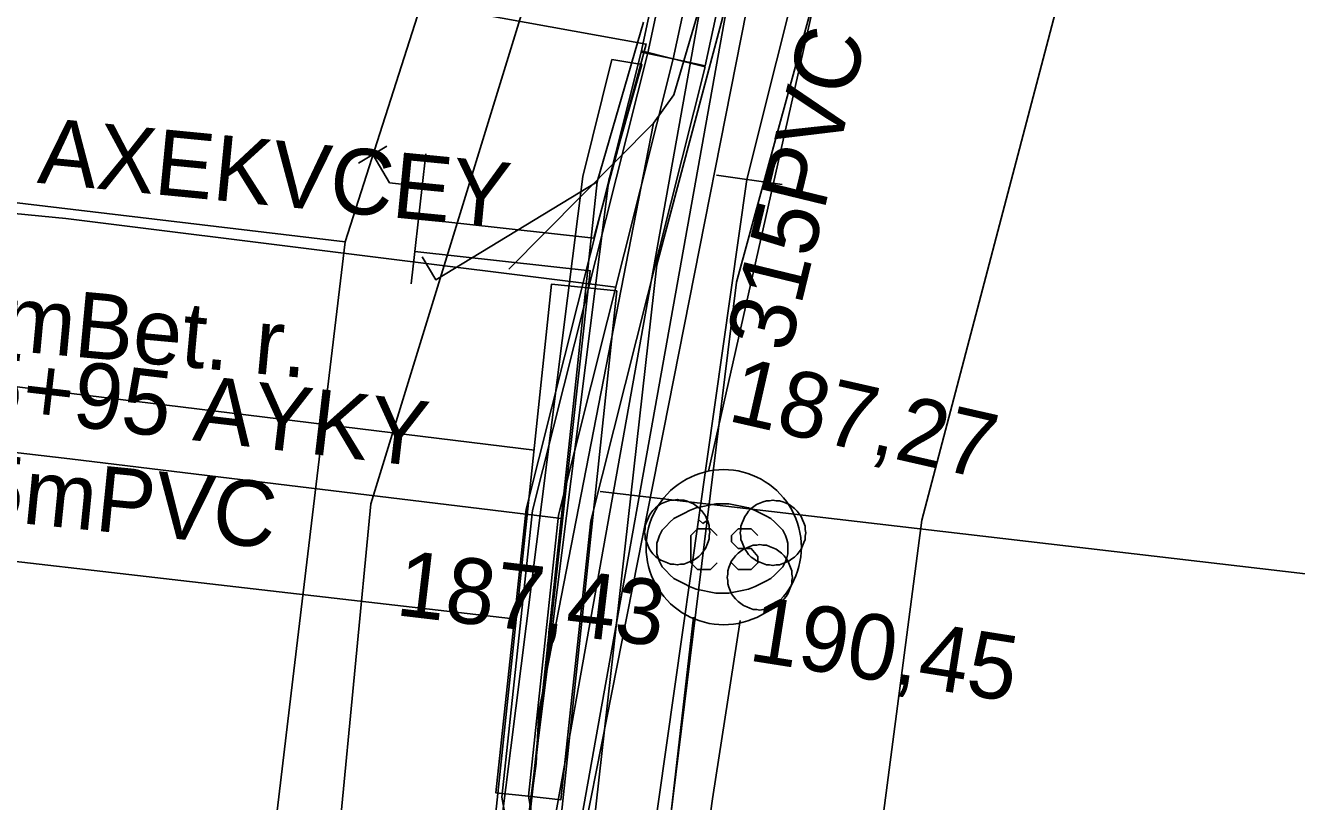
# Model space of a CAD drawing. Extents: x -746464 to -745690, y -1051581 to -1049993.
# Drawn here: x -746123.17 to -746103.78, y -1050733.16 to -1050721.32 of the extents above; entities that cross this region are included whole.
import ezdxf

# ---------------------------------------------------------------- set-up
doc = ezdxf.new("R2010")
doc.units = 0
for name, color, linetype in [('04_CETIN_neprovozovane', 7, 'Continuous'), ('04_CETIN_sdelovaci_podzem', 7, 'Continuous'), ('37_TVNET_sdelovaci_televizni kabely', 7, 'Continuous'), ('45_Eltodo_napajeci_kabel_NN', 7, 'Continuous'), ('45_Eltodo_vedeni_NN_zemni', 7, 'Continuous'), ('48_Prazs_plynarenska_STL', 7, 'Continuous'), ('51_PVaK_kanal_jednotna_overena poloha_rad', 7, 'Continuous'), ('51_PVaK_kanal_negravitacni_overena poloha', 7, 'Continuous'), ('51_PVaK_kanal_objekty', 7, 'Continuous'), ('51_PVaK_kanal_popisy', 7, 'Continuous'), ('51_PVaK_vodovod_chranicky_objekty', 7, 'Continuous'), ('51_PVaK_vodovod_NEPROVOZUJE PVK_neoverene poloha', 7, 'Continuous'), ('55_PREdi_chranicky', 7, 'Continuous'), ('55_PREdi_NN', 7, 'Continuous'), ('55_PREdi_NN_popisy', 7, 'Continuous'), ('55_PREdi_NN_pripojovaci_misto', 7, 'Continuous'), ('55_PREdi_stavby_popisy', 7, 'Continuous'), ('55_PREdi_VN', 7, 'Continuous'), ('55_PREdi_VN_popisy', 7, 'Continuous'), ('55_PREdi_ZRUSENE_elektro', 7, 'Continuous')]:
    doc.layers.add(name, color=color, linetype=linetype)

msp = doc.modelspace()

# ---------------------------------------------------------------- linework, layer by layer
at = {"layer": '04_CETIN_neprovozovane'}
msp.add_lwpolyline([(-746122.86, -1050802.08), (-746120.21, -1050779.57), (-746117.76, -1050758.96), (-746115.41, -1050737.5), (-746111.78, -1050719.1), (-746081.26, -1050611.75), (-746077.75, -1050600.04)], dxfattribs=at)
at = {"layer": '04_CETIN_sdelovaci_podzem'}
for points in [[(-746113.59, -1050722.81), (-746113.28, -1050722.38), (-746111.9, -1050717.67)], [(-746113.59, -1050722.81), (-746115.8, -1050725.04)], [(-746115.67, -1050734.71), (-746115.38, -1050732.58), (-746115.34, -1050731.79), (-746113.59, -1050722.81)]]:
    msp.add_lwpolyline(points, dxfattribs=at)
at = {"layer": '37_TVNET_sdelovaci_televizni kabely'}
for points in [[(-745984.595, -1050626.363), (-746079.15, -1050602.616), (-746117.902, -1050728.62), (-746140.499, -1050964.785), (-746150.343, -1051014.385), (-746134.374, -1051025.766), (-746053.56, -1051028.358)], [(-746118.296, -1050724.621), (-746094.89, -1050651.467), (-746102.801, -1050648.936)], [(-746121.771, -1050753.802), (-746119.076, -1050731.167), (-746118.296, -1050724.621), (-746124.842, -1050723.842)]]:
    msp.add_lwpolyline(points, dxfattribs=at)
at = {"layer": '45_Eltodo_napajeci_kabel_NN'}
msp.add_lwpolyline([(-746120.222, -1050780.456), (-746117.893, -1050761.331), (-746115.771, -1050739.469), (-746111.954, -1050718.14), (-746112.159, -1050718.76), (-746102.169, -1050679.37), (-746100.421, -1050672.083), (-746096.865, -1050659.485), (-746093.587, -1050648.313), (-746077.373, -1050597.206), (-746063.594, -1050600.606), (-746044.898, -1050606.017), (-746045.886, -1050609.461)], dxfattribs=at)
at = {"layer": '45_Eltodo_vedeni_NN_zemni'}
msp.add_lwpolyline([(-746116.168, -1050739.414), (-746112.348, -1050718.07)], dxfattribs=at)
at = {"layer": '48_Prazs_plynarenska_STL'}
msp.add_lwpolyline([(-746115.164, -1050775.276), (-746114.581, -1050769.606), (-746114.401, -1050767.848), (-746113.67, -1050760.737), (-746113.57, -1050759.76), (-746112.697, -1050753.167), (-746110.88, -1050739.44), (-746109.5, -1050728.87), (-746105.616, -1050714.089), (-746102.18, -1050701.01), (-746092.81, -1050669.78), (-746086.791, -1050645.246), (-746082.87, -1050630.67), (-746075.19, -1050609.92), (-746073.343, -1050606.911), (-746072.119, -1050604.92)], dxfattribs=at)
at = {"layer": '51_PVaK_kanal_jednotna_overena poloha_rad'}
msp.add_line((-746110.62, -1050718.65), (-746112.75, -1050728.12), dxfattribs=at)
msp.add_lwpolyline([(-746116.83, -1050763.77), (-746116.059, -1050757.073), (-746113.735, -1050736.907), (-746112.98, -1050730.35)], dxfattribs=at)
at = {"layer": '51_PVaK_kanal_negravitacni_overena poloha'}
msp.add_lwpolyline([(-746112.27, -1050730.4), (-746112.69, -1050733.12), (-746114.09, -1050743.18), (-746115.12, -1050753.61)], dxfattribs=at)
at = {"layer": '51_PVaK_kanal_objekty'}
for q in [(-746112.9, -1050728.86), (-746112.76, -1050728.86)]:
    msp.add_line((-746112.84, -1050728.92), q, dxfattribs=at)
msp.add_lwpolyline([(-746111.336, -1050729.28), (-746111.339, -1050729.354), (-746111.346, -1050729.428), (-746111.357, -1050729.502), (-746111.374, -1050729.574), (-746111.394, -1050729.646), (-746111.42, -1050729.716), (-746111.449, -1050729.784), (-746111.483, -1050729.85), (-746111.521, -1050729.914), (-746111.563, -1050729.976), (-746111.608, -1050730.034), (-746111.657, -1050730.09), (-746111.71, -1050730.143), (-746111.766, -1050730.192), (-746111.824, -1050730.238), (-746111.886, -1050730.279), (-746111.95, -1050730.317), (-746112.016, -1050730.351), (-746112.084, -1050730.38), (-746112.154, -1050730.406), (-746112.226, -1050730.426), (-746112.298, -1050730.443), (-746112.372, -1050730.454), (-746112.446, -1050730.461), (-746112.52, -1050730.464), (-746112.594, -1050730.461), (-746112.668, -1050730.454), (-746112.742, -1050730.443), (-746112.814, -1050730.426), (-746112.886, -1050730.406), (-746112.956, -1050730.38), (-746113.024, -1050730.351), (-746113.09, -1050730.317), (-746113.154, -1050730.279), (-746113.216, -1050730.238), (-746113.274, -1050730.192), (-746113.33, -1050730.143), (-746113.383, -1050730.09), (-746113.432, -1050730.034), (-746113.477, -1050729.976), (-746113.519, -1050729.914), (-746113.557, -1050729.85), (-746113.591, -1050729.784), (-746113.62, -1050729.716), (-746113.646, -1050729.646), (-746113.666, -1050729.574), (-746113.683, -1050729.502), (-746113.694, -1050729.428), (-746113.701, -1050729.354), (-746113.704, -1050729.28), (-746113.701, -1050729.206), (-746113.694, -1050729.132), (-746113.683, -1050729.058), (-746113.666, -1050728.986), (-746113.646, -1050728.914), (-746113.62, -1050728.844), (-746113.591, -1050728.776), (-746113.557, -1050728.71), (-746113.519, -1050728.646), (-746113.477, -1050728.584), (-746113.432, -1050728.526), (-746113.383, -1050728.47), (-746113.33, -1050728.417), (-746113.274, -1050728.368), (-746113.216, -1050728.323), (-746113.154, -1050728.281), (-746113.09, -1050728.243), (-746113.024, -1050728.209), (-746112.956, -1050728.18), (-746112.886, -1050728.154), (-746112.814, -1050728.134), (-746112.742, -1050728.117), (-746112.668, -1050728.106), (-746112.594, -1050728.099), (-746112.52, -1050728.096), (-746112.446, -1050728.099), (-746112.372, -1050728.106), (-746112.298, -1050728.117), (-746112.226, -1050728.134), (-746112.154, -1050728.154), (-746112.084, -1050728.18), (-746112.016, -1050728.209), (-746111.95, -1050728.243), (-746111.886, -1050728.281), (-746111.824, -1050728.323), (-746111.766, -1050728.368), (-746111.71, -1050728.417), (-746111.657, -1050728.47), (-746111.608, -1050728.526), (-746111.563, -1050728.584), (-746111.521, -1050728.646), (-746111.483, -1050728.71), (-746111.449, -1050728.776), (-746111.42, -1050728.844), (-746111.394, -1050728.914), (-746111.374, -1050728.986), (-746111.357, -1050729.058), (-746111.346, -1050729.132), (-746111.339, -1050729.206)], close=True, dxfattribs=at)
for points in [[(-746112.73, -1050729.05), (-746112.74, -1050729), (-746112.74, -1050728.95), (-746112.76, -1050728.9), (-746112.78, -1050728.85), (-746112.8, -1050728.8), (-746112.83, -1050728.76), (-746112.86, -1050728.72), (-746112.9, -1050728.68), (-746112.94, -1050728.65), (-746112.98, -1050728.62), (-746113.03, -1050728.6), (-746113.08, -1050728.58), (-746113.13, -1050728.56), (-746113.18, -1050728.56), (-746113.23, -1050728.55), (-746113.28, -1050728.56), (-746113.33, -1050728.56), (-746113.38, -1050728.58), (-746113.43, -1050728.6), (-746113.48, -1050728.62), (-746113.52, -1050728.65), (-746113.56, -1050728.68), (-746113.6, -1050728.72), (-746113.63, -1050728.76), (-746113.66, -1050728.8), (-746113.68, -1050728.85), (-746113.7, -1050728.9), (-746113.72, -1050728.95), (-746113.72, -1050729), (-746113.73, -1050729.05), (-746113.72, -1050729.1), (-746113.72, -1050729.15), (-746113.7, -1050729.2), (-746113.68, -1050729.25), (-746113.66, -1050729.3), (-746113.63, -1050729.34), (-746113.6, -1050729.38), (-746113.56, -1050729.42), (-746113.52, -1050729.45), (-746113.48, -1050729.48), (-746113.43, -1050729.5), (-746113.38, -1050729.52), (-746113.33, -1050729.54), (-746113.28, -1050729.54), (-746113.23, -1050729.55), (-746113.18, -1050729.54), (-746113.13, -1050729.54), (-746113.08, -1050729.52), (-746113.03, -1050729.5), (-746112.98, -1050729.48), (-746112.94, -1050729.45), (-746112.9, -1050729.42), (-746112.86, -1050729.38), (-746112.83, -1050729.34), (-746112.8, -1050729.3), (-746112.78, -1050729.25), (-746112.76, -1050729.2), (-746112.74, -1050729.15), (-746112.74, -1050729.1), (-746112.73, -1050729.05)], [(-746111.27, -1050729.06), (-746111.28, -1050729.01), (-746111.28, -1050728.96), (-746111.3, -1050728.91), (-746111.32, -1050728.86), (-746111.34, -1050728.81), (-746111.37, -1050728.77), (-746111.4, -1050728.73), (-746111.44, -1050728.69), (-746111.48, -1050728.66), (-746111.52, -1050728.63), (-746111.57, -1050728.61), (-746111.62, -1050728.59), (-746111.67, -1050728.57), (-746111.72, -1050728.57), (-746111.77, -1050728.56), (-746111.82, -1050728.57), (-746111.87, -1050728.57), (-746111.92, -1050728.59), (-746111.97, -1050728.61), (-746112.02, -1050728.63), (-746112.06, -1050728.66), (-746112.1, -1050728.69), (-746112.14, -1050728.73), (-746112.17, -1050728.77), (-746112.2, -1050728.81), (-746112.22, -1050728.86), (-746112.24, -1050728.91), (-746112.26, -1050728.96), (-746112.26, -1050729.01), (-746112.27, -1050729.06), (-746112.26, -1050729.11), (-746112.26, -1050729.16), (-746112.24, -1050729.21), (-746112.22, -1050729.26), (-746112.2, -1050729.31), (-746112.17, -1050729.35), (-746112.14, -1050729.39), (-746112.1, -1050729.43), (-746112.06, -1050729.46), (-746112.02, -1050729.49), (-746111.97, -1050729.51), (-746111.92, -1050729.53), (-746111.87, -1050729.55), (-746111.82, -1050729.55), (-746111.77, -1050729.56), (-746111.72, -1050729.55), (-746111.67, -1050729.55), (-746111.62, -1050729.53), (-746111.57, -1050729.51), (-746111.52, -1050729.49), (-746111.48, -1050729.46), (-746111.44, -1050729.43), (-746111.4, -1050729.39), (-746111.37, -1050729.35), (-746111.34, -1050729.31), (-746111.32, -1050729.26), (-746111.3, -1050729.21), (-746111.28, -1050729.16), (-746111.28, -1050729.11), (-746111.27, -1050729.06)], [(-746113.54, -1050729.3), (-746113.54, -1050729.38), (-746113.52, -1050729.44), (-746113.5, -1050729.5), (-746113.46, -1050729.58), (-746113.4, -1050729.64), (-746113.34, -1050729.7), (-746113.28, -1050729.76), (-746113.2, -1050729.8), (-746113.12, -1050729.84), (-746113.04, -1050729.88), (-746112.94, -1050729.92), (-746112.84, -1050729.94), (-746112.74, -1050729.96), (-746112.64, -1050729.98), (-746112.54, -1050729.98), (-746112.44, -1050729.98), (-746112.34, -1050729.96), (-746112.24, -1050729.94), (-746112.14, -1050729.92), (-746112.04, -1050729.88), (-746111.96, -1050729.84), (-746111.88, -1050729.8), (-746111.8, -1050729.76), (-746111.74, -1050729.7), (-746111.68, -1050729.64), (-746111.62, -1050729.58), (-746111.58, -1050729.5), (-746111.56, -1050729.44), (-746111.54, -1050729.38), (-746111.54, -1050729.3), (-746111.54, -1050729.22), (-746111.56, -1050729.16), (-746111.58, -1050729.1), (-746111.62, -1050729.02), (-746111.68, -1050728.96), (-746111.74, -1050728.9), (-746111.8, -1050728.84), (-746111.88, -1050728.8), (-746111.96, -1050728.76), (-746112.04, -1050728.72), (-746112.14, -1050728.68), (-746112.24, -1050728.66), (-746112.34, -1050728.64), (-746112.44, -1050728.62), (-746112.54, -1050728.62), (-746112.64, -1050728.62), (-746112.74, -1050728.64), (-746112.84, -1050728.66), (-746112.94, -1050728.68), (-746113.04, -1050728.72), (-746113.12, -1050728.76), (-746113.2, -1050728.8), (-746113.28, -1050728.84), (-746113.34, -1050728.9), (-746113.4, -1050728.96), (-746113.46, -1050729.02), (-746113.5, -1050729.1), (-746113.52, -1050729.16), (-746113.54, -1050729.22), (-746113.54, -1050729.3)], [(-746112.62, -1050729.52), (-746112.72, -1050729.62), (-746112.92, -1050729.62), (-746113.02, -1050729.52), (-746113.02, -1050729.1), (-746112.92, -1050729), (-746112.72, -1050729), (-746112.62, -1050729.1)], [(-746112.4, -1050729.52), (-746112.3, -1050729.62), (-746112.1, -1050729.62), (-746112, -1050729.52), (-746112, -1050729.42), (-746112.1, -1050729.3), (-746112.3, -1050729.3), (-746112.4, -1050729.2), (-746112.4, -1050729.1), (-746112.3, -1050729), (-746112.1, -1050729), (-746112, -1050729.1)], [(-746111.47, -1050729.74), (-746111.48, -1050729.69), (-746111.48, -1050729.64), (-746111.5, -1050729.59), (-746111.52, -1050729.54), (-746111.54, -1050729.49), (-746111.57, -1050729.45), (-746111.6, -1050729.41), (-746111.64, -1050729.37), (-746111.68, -1050729.34), (-746111.72, -1050729.31), (-746111.77, -1050729.29), (-746111.82, -1050729.27), (-746111.87, -1050729.25), (-746111.92, -1050729.25), (-746111.97, -1050729.24), (-746112.02, -1050729.25), (-746112.07, -1050729.25), (-746112.12, -1050729.27), (-746112.17, -1050729.29), (-746112.22, -1050729.31), (-746112.26, -1050729.34), (-746112.3, -1050729.37), (-746112.34, -1050729.41), (-746112.37, -1050729.45), (-746112.4, -1050729.49), (-746112.42, -1050729.54), (-746112.44, -1050729.59), (-746112.46, -1050729.64), (-746112.46, -1050729.69), (-746112.47, -1050729.74), (-746112.46, -1050729.79), (-746112.46, -1050729.84), (-746112.44, -1050729.89), (-746112.42, -1050729.94), (-746112.4, -1050729.99), (-746112.37, -1050730.03), (-746112.34, -1050730.07), (-746112.3, -1050730.11), (-746112.26, -1050730.14), (-746112.22, -1050730.17), (-746112.17, -1050730.19), (-746112.12, -1050730.21), (-746112.07, -1050730.23), (-746112.02, -1050730.23), (-746111.97, -1050730.24), (-746111.92, -1050730.23), (-746111.87, -1050730.23), (-746111.82, -1050730.21), (-746111.77, -1050730.19), (-746111.72, -1050730.17), (-746111.68, -1050730.14), (-746111.64, -1050730.11), (-746111.6, -1050730.07), (-746111.57, -1050730.03), (-746111.54, -1050729.99), (-746111.52, -1050729.94), (-746111.5, -1050729.89), (-746111.48, -1050729.84), (-746111.48, -1050729.79), (-746111.47, -1050729.74)]]:
    msp.add_lwpolyline(points, dxfattribs=at)
at = {"layer": '51_PVaK_vodovod_chranicky_objekty'}
msp.add_line((-746111.63, -1050723.747), (-746112.63, -1050723.605), dxfattribs=at)
at = {"layer": '51_PVaK_vodovod_NEPROVOZUJE PVK_neoverene poloha'}
for points in [[(-746081.419, -1050615.368), (-746089.682, -1050643.328), (-746097.066, -1050667.122), (-746097.128, -1050667.322), (-746108.564, -1050709.28), (-746112.17, -1050723.67)], [(-746112.17, -1050723.67), (-746115.962, -1050750.386), (-746116.764, -1050758.266), (-746119.36, -1050777.72)]]:
    msp.add_lwpolyline(points, dxfattribs=at)
at = {"layer": '55_PREdi_chranicky'}
for points in [[(-746099.15, -1050668.69), (-746098.675, -1050668.846), (-746100.87, -1050675.512), (-746102.387, -1050681.318), (-746103.889, -1050686.926), (-746105.384, -1050691.978), (-746106.221, -1050696.346), (-746107.647, -1050702.28), (-746109.299, -1050707.795), (-746111.804, -1050717.296), (-746112.801, -1050721.935), (-746113.29, -1050721.83), (-746113.779, -1050721.725), (-746112.776, -1050717.064), (-746110.261, -1050707.525), (-746108.613, -1050702.02), (-746107.199, -1050696.134), (-746106.356, -1050691.742), (-746104.851, -1050686.654), (-746103.353, -1050681.062), (-746101.83, -1050675.228), (-746099.625, -1050668.534), (-746099.15, -1050668.69)], [(-746113.29, -1050721.83), (-746112.805, -1050721.952), (-746114.547, -1050728.878), (-746115.003, -1050733.133), (-746115.5, -1050733.08), (-746115.997, -1050733.027), (-746115.533, -1050728.702), (-746113.775, -1050721.708), (-746113.29, -1050721.83)], [(-746114.225, -1050721.84), (-746113.769, -1050721.915), (-746114.275, -1050723.682), (-746115.92, -1050736.748), (-746116.316, -1050736.698), (-746114.668, -1050723.626), (-746114.225, -1050721.84)], [(-746115.201, -1050735.314), (-746116.195, -1050735.209), (-746115.145, -1050725.265), (-746114.151, -1050725.37), (-746115.201, -1050735.314)]]:
    msp.add_lwpolyline(points, close=True, dxfattribs=at)
at = {"layer": '55_PREdi_NN'}
for points in [[(-746079.707, -1050608.094), (-746081.337, -1050613.521), (-746088.598, -1050639.168), (-746100.883, -1050680.307), (-746109.804, -1050710.935), (-746113.542, -1050724.97), (-746114.797, -1050736.143), (-746116.957, -1050755.942), (-746121.273, -1050791.507), (-746121.329, -1050792.488), (-746122.44, -1050801.822), (-746124.772, -1050826.479), (-746132.514, -1050898.319), (-746135.263, -1050933.408), (-746137.115, -1050954.341), (-746141.612, -1050953.806)], [(-746078.666, -1050608.367), (-746080.547, -1050614.642), (-746087.42, -1050639.673), (-746099.733, -1050680.532), (-746108.682, -1050711.888), (-746112.327, -1050725.235), (-746113.87, -1050737.785), (-746116.087, -1050756.251), (-746119.869, -1050789.369)], [(-746120.05, -1050717.181), (-746120.127, -1050717.683), (-746120.518, -1050717.621), (-746120.967, -1050720.285), (-746113.702, -1050721.603), (-746114.501, -1050724.567), (-746117.176, -1050724.271)], [(-746113.746, -1050721.267), (-746114.449, -1050723.706)], [(-746117.286, -1050725.264), (-746117.231, -1050724.767), (-746117.176, -1050724.271), (-746117.12, -1050723.774), (-746117.065, -1050723.277)], [(-746117.12, -1050723.774), (-746117.617, -1050723.719)], [(-746114.449, -1050723.706), (-746115.673, -1050735.132), (-746117.214, -1050749.815)], [(-746117.122, -1050724.851), (-746116.912, -1050725.198), (-746114.449, -1050723.706)], [(-746117.231, -1050724.767), (-746114.556, -1050725.063), (-746115.751, -1050735.863), (-746117.126, -1050749.478), (-746125.289, -1050748.581), (-746125.093, -1050747.151), (-746125.515, -1050747.066), (-746125.379, -1050746.39)]]:
    msp.add_lwpolyline(points, dxfattribs=at)
at = {"layer": '55_PREdi_NN_popisy'}
msp.add_lwpolyline([(-746131.372, -1050726.9), (-746122.496, -1050727.933), (-746114.994, -1050728.841)], dxfattribs=at)
at = {"layer": '55_PREdi_NN_pripojovaci_misto'}
for p, q in [((-746117.66, -1050723.162), (-746118.089, -1050723.419)), ((-746117.617, -1050723.719), (-746117.875, -1050723.29))]:
    msp.add_line(p, q, dxfattribs=at)
at = {"layer": '55_PREdi_stavby_popisy'}
for points in [[(-746134.38, -1050725.766), (-746124.676, -1050726.666), (-746115.407, -1050727.798)], [(-746114.407, -1050728.431), (-746103.339, -1050729.722), (-746093.662, -1050730.881)], [(-746130.442, -1050728.692), (-746129.447, -1050728.792), (-746115.771, -1050730.369)]]:
    msp.add_lwpolyline(points, dxfattribs=at)
at = {"layer": '55_PREdi_VN'}
for points in [[(-746119.82, -1050775.83), (-746119.1, -1050768.57), (-746117.99, -1050758.17), (-746117.59, -1050754.39), (-746116.84, -1050747.88), (-746116.1, -1050741.93), (-746115.26, -1050735.57), (-746115.23, -1050734.58), (-746115.5, -1050733.08), (-746115.04, -1050728.79), (-746113.29, -1050721.83), (-746112.29, -1050717.18), (-746109.78, -1050707.66), (-746108.13, -1050702.15), (-746106.71, -1050696.24), (-746105.87, -1050691.86), (-746104.37, -1050686.79), (-746102.87, -1050681.19), (-746101.35, -1050675.37)], [(-746101.35, -1050675.37), (-746102.87, -1050681.19), (-746104.37, -1050686.79), (-746105.87, -1050691.86), (-746106.71, -1050696.24), (-746108.13, -1050702.15), (-746109.78, -1050707.66), (-746112.29, -1050717.18), (-746113.29, -1050721.83), (-746115.04, -1050728.79), (-746115.5, -1050733.08), (-746115.23, -1050734.58), (-746115.26, -1050735.57), (-746116.1, -1050741.93), (-746116.84, -1050747.88), (-746117.59, -1050754.39), (-746117.99, -1050758.17), (-746119.1, -1050768.57), (-746119.82, -1050775.83)]]:
    msp.add_lwpolyline(points, dxfattribs=at)
at = {"layer": '55_PREdi_VN_popisy'}
msp.add_lwpolyline([(-746134.35, -1050723.117), (-746122.556, -1050724.264), (-746114.165, -1050725.31)], dxfattribs=at)
at = {"layer": '55_PREdi_ZRUSENE_elektro'}
msp.add_lwpolyline([(-746120.218, -1050775.786), (-746119.498, -1050768.529), (-746118.388, -1050758.128), (-746117.988, -1050754.346), (-746117.237, -1050747.832), (-746116.497, -1050741.879), (-746115.659, -1050735.538), (-746115.631, -1050734.61), (-746115.904, -1050733.094), (-746115.435, -1050728.72), (-746113.68, -1050721.739), (-746112.679, -1050717.087), (-746110.165, -1050707.552), (-746108.516, -1050702.046), (-746107.101, -1050696.156), (-746106.259, -1050691.765), (-746104.755, -1050686.681), (-746103.257, -1050681.088), (-746101.734, -1050675.257)], dxfattribs=at)

# ---------------------------------------------------------------- texts
at = {"layer": '51_PVaK_kanal_popisy'}
for s, rotation, p in [('315PVC', 76.3239, (-746111.519, -1050726.333)), ('187,27', 347.1482, (-746112.482, -1050727.346)), ('187,43', 353.2525, (-746117.541, -1050730.315)), ('190,45', 351.0438, (-746112.163, -1050731.005))]:
    msp.add_text(s, height=1, rotation=rotation, dxfattribs=at).set_placement(p)
at = {"layer": '55_PREdi_NN_popisy'}
msp.add_text('3x185+95 AYKY', height=1, rotation=353.3602, dxfattribs=at).set_placement((-746126.876, -1050726.919))
at = {"layer": '55_PREdi_stavby_popisy'}
for s, rotation, p in [('2x20-15.0mBet. r.', 354.7013, (-746129.482, -1050725.718)), ('1x200-11,5mPVC', 354.2534, (-746129.895, -1050728.245))]:
    msp.add_text(s, height=1, rotation=rotation, dxfattribs=at).set_placement(p)
at = {"layer": '55_PREdi_VN_popisy'}
msp.add_text('3x1x120 AXEKVCEY', height=1, rotation=354.442, dxfattribs=at).set_placement((-746128.405, -1050723.193))

doc.saveas('drawing.dxf')
